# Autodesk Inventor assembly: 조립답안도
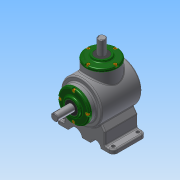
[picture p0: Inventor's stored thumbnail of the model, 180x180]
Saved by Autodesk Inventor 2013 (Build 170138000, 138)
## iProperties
Created: 2018-08
Part Number: 조립답안도
Document SubType Name: Assembly
Designer: Administrator
Author: Administrator
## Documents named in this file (14)
- C:\Users\Administrator\Desktop\480808V1022\조립답안도.iam
- C:\Users\Administrator\Desktop\480808V1022\본체.ipt
- C:\Users\Administrator\Desktop\480808V1022\메인 축.ipt
- 메인 축.ipt
- C:\Users\Administrator\Desktop\480808V1022\베어링 6203.ipt
- C:\Users\Administrator\Desktop\480808V1022\키 5x5.ipt
- C:\Users\Administrator\Desktop\480808V1022\메인 베벨기어.ipt
- C:\Users\Administrator\Desktop\480808V1022\커버.ipt
- C:\Users\Administrator\Desktop\480808V1022\오일실 17 32 8.ipt
- C:\Users\Administrator\Desktop\480808V1022\볼트 M4.ipt
- C:\Users\Administrator\Desktop\480808V1022\서브 축.ipt
- 서브 축.ipt
- C:\Users\Administrator\Desktop\480808V1022\서브 베벨기어.ipt
- C:\Users\Administrator\Desktop\480808V1022\키 4x4.ipt
